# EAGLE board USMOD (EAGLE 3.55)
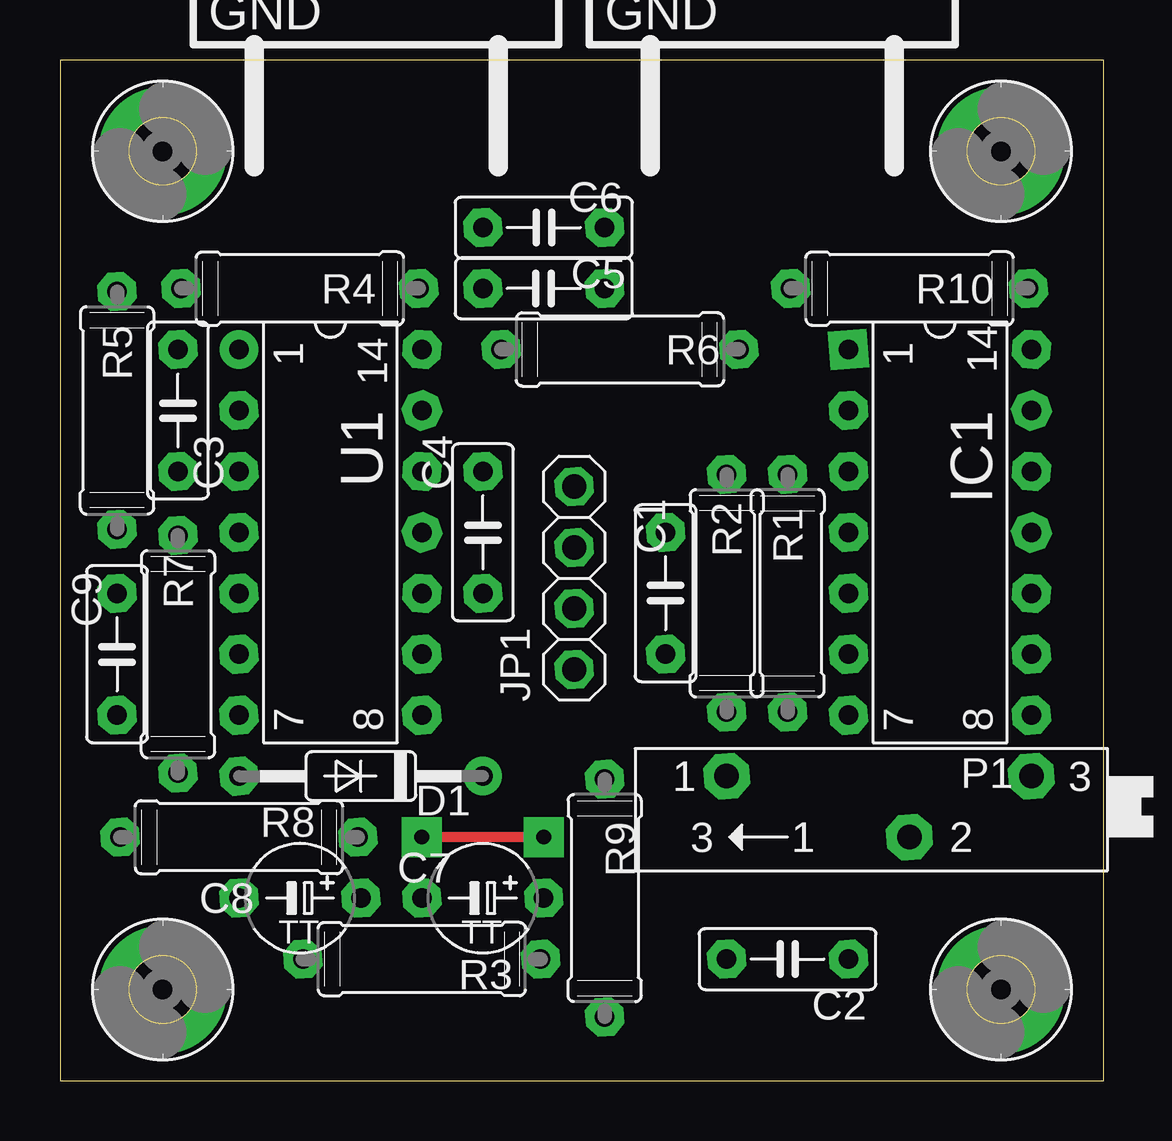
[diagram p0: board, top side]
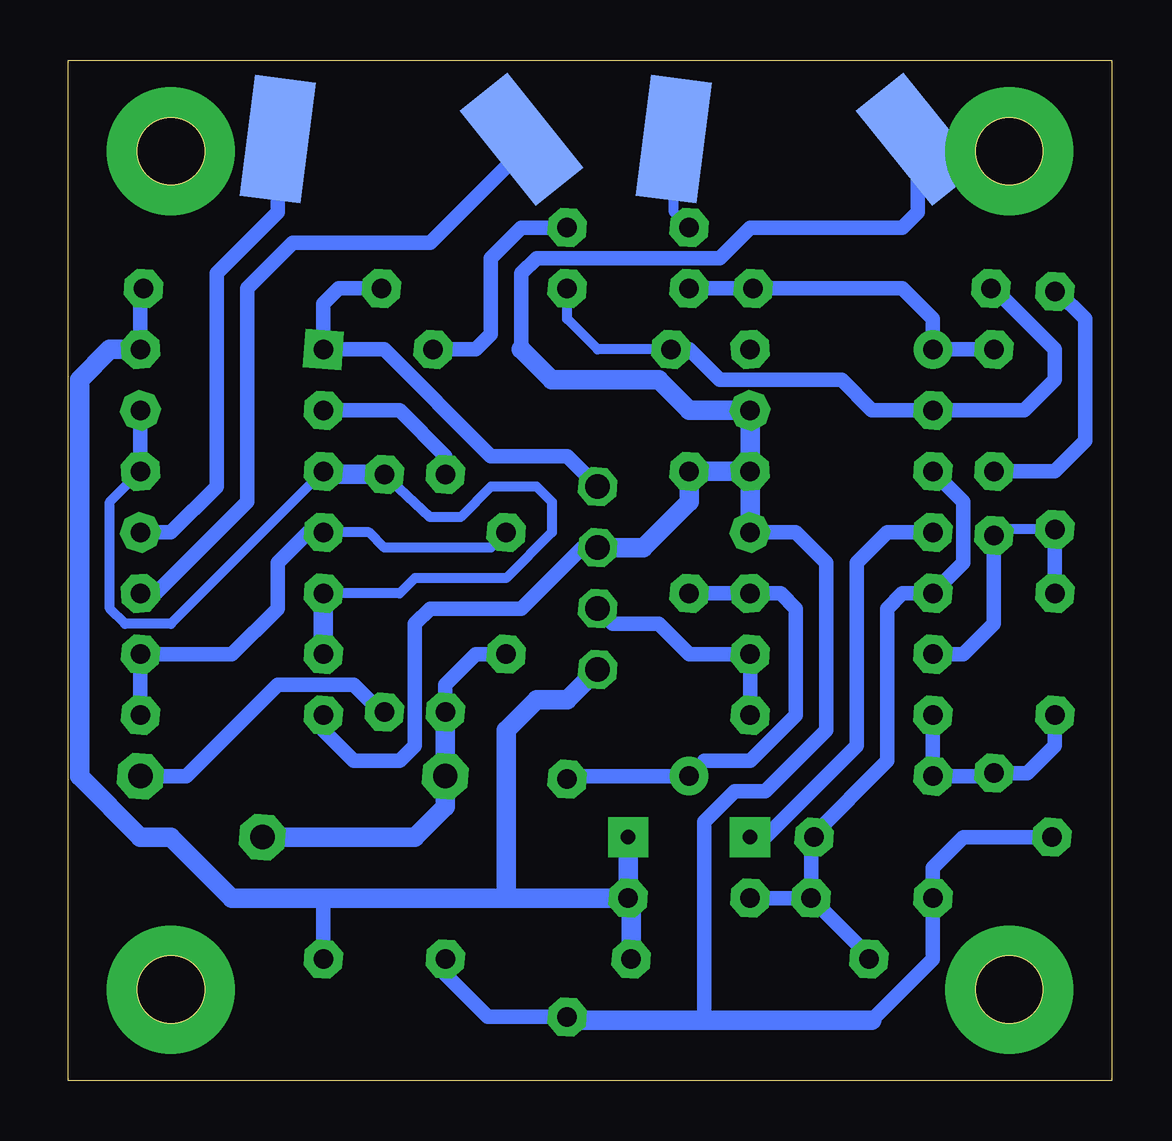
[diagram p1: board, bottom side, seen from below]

Size 43.48 x 42.53 mm. Coordinates in mm from the lower left corner, seen from the top.
Outline: 0,0 43.48,0 43.48,42.53 0,42.53 0,0
Copper layers used: Top, Bottom

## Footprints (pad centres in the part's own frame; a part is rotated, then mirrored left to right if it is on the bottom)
B2,5 = drill 0.813 pad 1.6 octagon:  -2.54,0;  2.54,0
P5-45 = drill 0.813 pad 1.6 octagon:  -2.54,0;  2.54,0
35-10 = drill 0.813 pad 1.6 round:  -5.08,0 | drill 0.813 pad 1.6 octagon:  5.08,0
L14 = drill 0.813 pad 1.6 square:  -7.62,-3.81 | drill 0.813 pad 1.6 octagon:  -5.08,-3.81;  7.62,-3.81;  7.62,3.81;  -2.54,-3.81;  0,-3.81;  5.08,-3.81;  2.54,-3.81;  5.08,3.81;  2.54,3.81;  0,3.81;  -2.54,3.81;  -5.08,3.81;  -7.62,3.81
04 = drill 1.016 pad 1.6 octagon:  -3.81,0;  -1.27,0;  1.27,0;  3.81,0
19L = drill 1.016 pad 1.905 octagon:  7.62,0;  -5.08,0;  0,2.54
2,8-P = drill 2.794 pad 5.334 round: 8 0,0
09/10 = drill 0.813 pad 1.6 octagon:  -4.953,0;  4.953,0
L14' = drill 0.813 pad 1.6 round:  -7.62,-3.81 | drill 0.813 pad 1.6 octagon:  -5.08,-3.81;  -2.54,-3.81;  0,-3.81;  2.54,-3.81;  5.08,-3.81;  7.62,-3.81;  7.62,3.81;  5.08,3.81;  2.54,3.81;  0,3.81;  -2.54,3.81;  -5.08,3.81;  -7.62,3.81
_TRANS = smd 2.54 x 5.08 rotated 321.2 bottom:  -5.08,-10.287 | smd 2.54 x 5.08 rotated 7.3 bottom:  5.08,-10.287

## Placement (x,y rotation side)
C1  150p  [B2,5]  25.23,20.32 90 top
C2  100n  [B2,5]  30.32,5.08 0 top
C3  10n  [B2,5]  4.92,27.94 270 top
C4  100n  [B2,5]  17.62,22.86 270 top
C5  10p  [B2,5]  20.16,33.02 180 top
C6  100n  [B2,5]  20.16,35.55 0 top
C7  4,7u  [P5-45]  17.62,7.62 0 top
C8  4,7u  [P5-45]  10,7.62 0 top
C9  10p  [B2,5]  2.38,17.78 270 top
D1  1N4148  [35-10]  12.54,12.69 180 top
IC1  4001  [L14]  36.66,22.86 270 top
JP1  PINHD-1X4  [04]  21.43,20.95 90 top
P1  20k  [19L]  35.4,12.69 180 top
PAD1  BO2,8P  [2,8-P]  4.28,3.81 0 top
PAD2  BO2,8P  [2,8-P]  39.2,3.81 0 top
PAD3  BO2,8P  [2,8-P]  39.2,38.73 0 top
PAD4  BO2,8P  [2,8-P]  4.28,38.73 0 top
R1  470k  [09/10]  27.78,20.32 270 top
R2  39k  [09/10]  30.32,20.32 90 top
R3  4,7k  [09/10]  15.08,5.08 0 top
R4  56k  [09/10]  10,33.02 0 top
R5  4,7k  [09/10]  2.38,27.94 270 top
R6  3,9k  [09/10]  23.33,30.48 180 top
R7  180k  [09/10]  4.92,17.78 270 top
R8  4,7k  [09/10]  7.46,10.15 0 top
R9  22k  [09/10]  22.7,7.62 90 top
R10  22k  [09/10]  35.4,33.02 0 top
U1  TL084N  [L14']  11.27,22.86 270 top
W1  UST-40T  [_TRANS]  29.68,49.52 0 top
W2  UST-40R  [_TRANS]  13.17,49.52 0 top

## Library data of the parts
C1-C6 C9 = cap
C7 C8 = cap-tant
D1 = diode
IC1 = 40xx
JP1 = pinhead
P1 = trimpot
PAD1-PAD4 = holes
R1-R10 = r
U1 = linear
W1 W2 = sensor

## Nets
+5V: C2. C7. IC1. JP1. R3. R10. U1.
GND: C2. C4. C8. IC1. JP1. R8. R9. U1. W2.
N$1: IC1. R2.
N$2: IC1. JP1. R10.
N$3: C1. IC1.
N$4: IC1. R1.
N$5: IC1. W1.
N$6: IC1. W1.
N$7: P1. R2.
N$9: C1. P1. R1.
N$10: C6. R6.
N$11: C7. C8. R3. R8. U1.
N$12: C6. W2.
N$13: C5. R4. R6. U1.
N$14: C3. C5. R4. U1.
N$17: C3. R5.
N$18: C9. R5. R7. U1.
N$19: C9. D1. R7. U1.
N$22: JP1. U1.
N$23: C4. D1. R9. U1.

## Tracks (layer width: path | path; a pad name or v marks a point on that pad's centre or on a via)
+5V  (via drill 0.61 pad 1.68)
  Top 0.406: v20.16,10.15 v15.08,10.15
  Bottom 0.406: 40.48,33.02 R10. | 20.03,7.49 C7.
  Bottom 0.61: IC1. 40.48,33.02 | 32.86,7.62 C2. | 7.46,22.86 9.36,22.86 10.63,21.59 10.63,13.96 14.44,10.15 v15.08,10.15
  Bottom 0.813: IC1. 41.74,30.48 43.02,29.21 43.02,12.69 40.48,10.15 39.2,10.15 36.66,7.62 32.86,7.62 25.23,7.62 | 21.43,17.14 22.7,15.87 23.96,15.87 25.23,14.6 25.23,7.62 | 25.23,7.62 C7. v20.16,10.15 | R3. 20.03,7.49
GND
  Bottom 0.406: 22.7,2.54 22.7,2.66
  Bottom 0.61: 8.09,39.24 8.09,36.19 8.73,35.55 15.08,35.55 16.35,34.28 23.96,34.28 24.6,33.65 24.6,30.48 | 32.86,15.23 32.86,14.6 31.59,13.33 29.68,13.33 29.05,13.96 29.05,19.05 28.41,19.68 24.6,19.68 22.06,22.22 21.43,22.22 | 15.08,22.86 13.17,22.86 11.9,21.59 11.9,14.6 14.44,12.06 15.71,12.06 16.98,10.79 16.98,2.54 | 22.7,2.66 26,2.66 27.78,4.44 27.78,5.08 | 2.5,10.15 6.18,10.15 7.46,8.88 7.46,7.62 7.46,5.08 10,2.54
  Bottom 0.813: 15.08,25.39 17.62,25.39 17.62,24.12 19.52,22.22 21.43,22.22 | 15.08,25.39 15.08,27.94 17.62,27.94 18.89,29.21 23.33,29.21 24.6,30.48 | 15.08,22.86 15.08,25.39 | 10,2.54 16.98,2.54 22.7,2.54
N$1
  Bottom 0.406: R2. 28.41,23.49 27.14,23.49 25.87,24.76 23.96,24.76 23.33,24.12 23.33,22.86 25.23,20.95 29.05,20.95 29.68,20.32 32.86,20.32 | 32.73,25.27 32.86,25.39 39.2,19.05 41.11,19.05 41.74,19.68 41.74,24.12 40.48,25.39
  Bottom 0.61: 40.48,25.39 40.48,27.94
  Bottom 0.813: R2. 32.73,25.27 | 32.86,20.32 32.86,17.78
N$2
  Bottom 0.406: 30.44,33.02 30.32,33.02
  Bottom 0.61: 30.44,33.02 32.22,33.02 32.86,32.38 32.86,30.48 30.32,30.48 25.87,26.03 22.7,26.03 JP1.
N$3
  Bottom 0.406: C1. 25.87,22.22 30.32,22.22 30.95,22.86 32.86,22.86
  Bottom 0.61: 40.48,15.23 40.48,17.78 36.66,17.78 34.76,19.68 34.76,21.59 33.49,22.86 32.86,22.86
N$4
  Bottom 0.406: 27.78,25.27 27.78,26.03
  Bottom 0.61: 27.78,26.03 29.68,27.94 32.86,27.94
N$5
  Bottom 0.406: W1. 35.4,39.36
  Bottom 0.61: 40.48,22.86 39.2,22.86 37.3,24.76 37.3,33.65 34.76,36.19 W1.
N$6
  Bottom 0.406: 25.23,39.36 24.6,39.24 25.23,38.09
  Bottom 0.61: 40.48,20.32 39.84,20.32 36.03,24.12 36.03,33.02 34.12,34.92 28.41,34.92 25.23,38.09
N$7
  Bottom 0.406: 30.32,15.36 30.44,15.36
  Bottom 0.61: 30.44,15.36 31.59,16.51 34.76,16.51 38.57,12.69 40.48,12.69
N$9
  Bottom 0.406: R1. 27.78,15.23
  Bottom 0.61: 25.23,17.78 26.51,17.78 27.78,16.51 R1.
  Bottom 0.813: R1. 27.78,12.69 27.78,11.42 29.05,10.15 P1.
N$10
  Bottom 0.406: 28.28,30.48 27.78,30.48
  Bottom 0.61: C6. 24.6,35.55 25.87,34.28 25.87,31.11 26.51,30.48 28.28,30.48
N$11
  Bottom 0.406: 10.12,5.08 10.12,5.2 | 12.54,10.15 R8.
  Bottom 0.61: 7.46,25.39 6.18,24.12 6.18,21.59 7.46,20.32 8.73,20.32 9.36,19.68 9.36,13.33 12.54,10.15 C8. | C8. 15.08,7.62 | 10.12,5.2 C8.
N$12
  Bottom 0.406: 17.62,39.36 W2. 18.25,36.19 17.62,35.55
N$13
  Bottom 0.406: 17.62,30.48 R6. 21.43,30.48 22.7,31.75 22.7,33.02 | 4.92,33.02 5.04,33.02
  Bottom 0.61: 17.62,30.48 16.35,29.21 11.27,29.21 10,27.94 7.46,27.94 3.65,27.94 2.38,29.21 2.38,30.48 4.92,33.02
N$14
  Bottom 0.61: C5. R4. 8.73,33.02 7.46,31.75 7.46,30.48 4.92,30.48
N$17
  Bottom 0.406: 2.25,32.89 2.38,32.89
  Bottom 0.61: 2.25,32.89 1.1,31.75 1.1,26.67 2.38,25.39 C3.
N$18
  Bottom 0.406: R5. 4.92,22.98 4.92,22.73
  Bottom 0.61: 2.38,20.32 R5. | 4.92,22.73 4.92,19.05 6.18,17.78 7.46,17.78
N$19
  Bottom 0.406: R7. 4.92,12.69
  Bottom 0.61: 7.46,15.23 D1. 4.92,12.69 | R7. 3.52,12.82 2.38,13.96 C9.
N$22
  Bottom 0.61: 15.08,15.23 15.08,17.78 17.62,17.78 18.89,19.05 20.79,19.05 21.43,19.68
N$23
  Bottom 0.406: 15.08,20.32 C4. | 16.98,13.33 17.62,12.69 | 22.7,12.69 R9.
  Bottom 0.61: C4. 15.08,20.32 13.81,20.32 13.17,19.68 13.17,15.23 15.08,13.33 16.98,13.33 | 17.62,12.69 22.7,12.69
